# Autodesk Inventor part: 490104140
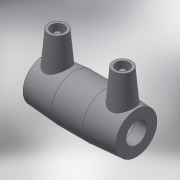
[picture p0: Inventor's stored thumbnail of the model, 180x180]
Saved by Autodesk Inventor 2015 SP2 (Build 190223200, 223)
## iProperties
Created: 2017-06
Part Number: 490104140
Material: Generic
Description: PLASSON COUPLER 140-140
Document SubType Name: Modeling
Designer: KIM
Mass: 55.0731 g
Surface Area: 148.067 cm^2
Volume: 55.0731 cm^3
Density: 1 g/cm^3
Appearance: Default
Author: KIM
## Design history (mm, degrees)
derived "490104.ipt"
feature "Solid1::490104.ipt"
tag "TaggingFeature1"
body "Solid1"
other parameters: "d0" = 183, "d2" = 174, "d4" = 61, "d5" = 156.6, "d6" = 133, "d8" = 168 deg, "d10" = 36, "d11" = 12, "d13" = 183, "d14" = 17.6296, "d17" = 133, "d19" = 3.52592, "d20" = 168 deg, "d22" = 163.56, "d23" = 174, "d24" = 158.6532, "d25" = 135 deg, "d26" = 73.2, "d27" = 135 deg, "d29" = 97, "d30" = 14, "d31" = 64.05, "d34" = 5 deg, "d35" = 15, "d39" = 5 deg, "d41" = 4, "d42" = 14, "d43" = 0, "d45" = 4, "d46" = 14, "d47" = 0, "d48" = 3, "d49" = 0, "d50" = 3, "d51" = 0, "d52" = 26.1, "d53" = 6.525, "L_" = 183, "D_" = 174, "A_" = 97, "d_2" = 12
